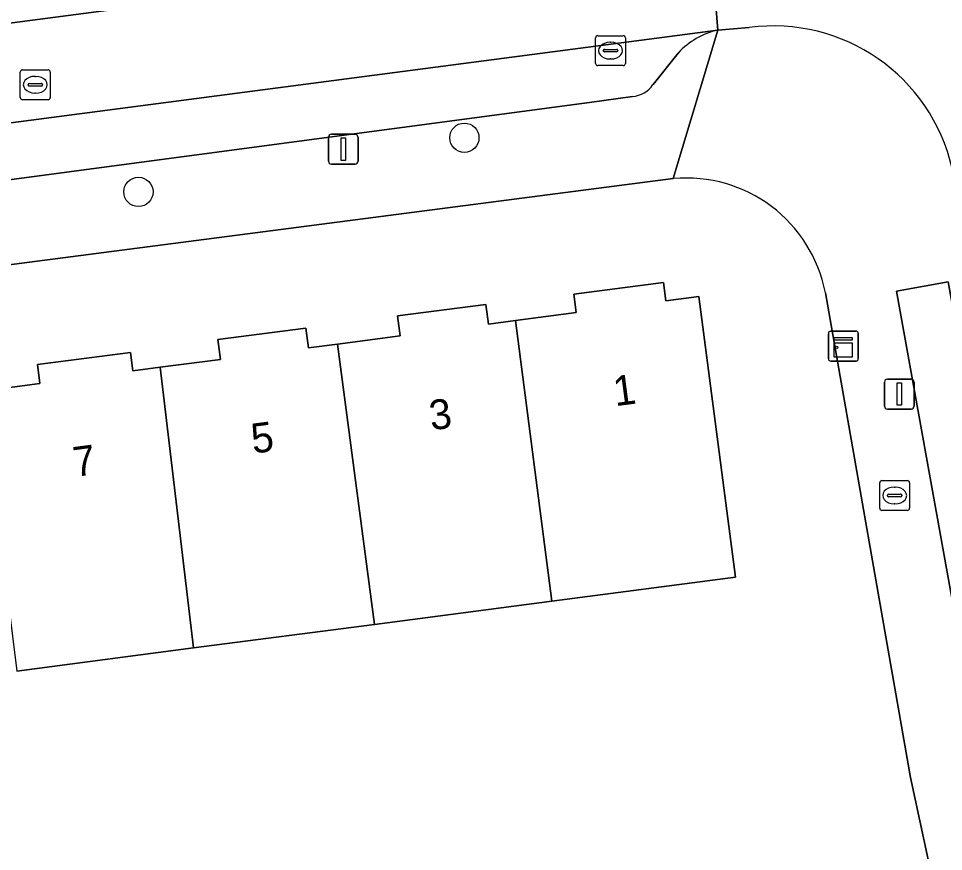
# Model space of a CAD drawing. Extents: x 162073 to 163043, y 381818 to 382561.
# Drawn here: x 162440.71 to 162471.64, y 382437.39 to 382465.27 of the extents above; entities that cross this region are included whole.
import ezdxf

# ---------------------------------------------------------------- set-up
doc = ezdxf.new("R2010")
doc.units = 0
for name, color, linetype in [('IMGEO_Boom', 7, 'Continuous'), ('IMGEO_Brandkraan', 7, 'Continuous'), ('IMGEO_Erf', 7, 'Continuous'), ('IMGEO_Kast', 7, 'Continuous'), ('IMGEO_Kolk', 7, 'Continuous'), ('IMGEO_Lichtmast', 7, 'Continuous'), ('IMGEO_Pand', 7, 'Continuous'), ('IMGEO_Pand_nummerreeks', 7, 'Continuous'), ('IMGEO_Parkeervlak_open', 7, 'Continuous'), ('IMGEO_Rijbaan_lokaal_open', 7, 'Continuous'), ('IMGEO_Rioolput', 7, 'Continuous'), ('IMGEO_Voetpad_open', 7, 'Continuous')]:
    doc.layers.add(name, color=color, linetype=linetype)

msp = doc.modelspace()

# ---------------------------------------------------------------- linework, layer by layer
at = {"layer": 'IMGEO_Boom'}
for centre in [(162455.618, 382461.278), (162444.718, 382459.465)]:
    msp.add_circle(centre, 0.489, dxfattribs=at)
at = {"layer": 'IMGEO_Brandkraan'}
for p, q in [((162469.51, 382448.881), (162469.51, 382449.733)), ((162469.585, 382449.807), (162470.437, 382449.807)), ((162469.998, 382449.587), (162470.023, 382449.587)), ((162470.511, 382449.733), (162470.511, 382448.881)), ((162469.769, 382449.301), (162469.769, 382449.313)), ((162470.207, 382449.264), (162469.809, 382449.264)), ((162469.812, 382449.35), (162470.21, 382449.35)), ((162470.253, 382449.313), (162470.253, 382449.301)), ((162470.021, 382449.027), (162469.996, 382449.027)), ((162470.437, 382448.807), (162469.585, 382448.807))]:
    msp.add_line(p, q, dxfattribs=at)
for points in [[(162469.51, 382448.881), (162469.51, 382449.733)], [(162469.585, 382449.807), (162470.437, 382449.807)], [(162470.511, 382449.733), (162470.511, 382448.881)], [(162470.437, 382448.807), (162469.585, 382448.807)]]:
    msp.add_lwpolyline(points, dxfattribs=at)
for centre, radius, start, end in [((162469.587, 382449.731), 0.0765, 91.552, 178.448), ((162469.587, 382449.731), 0.0765, 91.552, 178.448), ((162470.435, 382449.731), 0.0765, 1.552, 88.448), ((162470.435, 382449.731), 0.0765, 1.552, 88.448), ((162469.809, 382449.31), 0.0403, 85.8775, 175.7526), ((162469.806, 382449.3), 0.0366, 178.938, 274.7102), ((162470.21, 382449.307), 0.043, 264.8664, 352.4533), ((162470.214, 382449.312), 0.0386, 1.7309, 96.639), ((162469.587, 382448.883), 0.0765, 181.552, 268.448), ((162469.587, 382448.883), 0.0765, 181.552, 268.448), ((162470.435, 382448.883), 0.0765, 271.552, 358.448), ((162470.435, 382448.883), 0.0765, 271.552, 358.448)]:
    msp.add_arc(centre, radius, start, end, dxfattribs=at)
for centre, major_axis, ratio, start_param, end_param in [((162469.997, 382449.307), (-0.387, 0.002), 0.722429, 4.712389, 7.853982), ((162470.022, 382449.307), (-0.39, 0.002), 0.717154, 1.570796, 4.712389)]:
    msp.add_ellipse(centre, major_axis=major_axis, ratio=ratio, start_param=start_param, end_param=end_param, dxfattribs=at)
at = {"layer": 'IMGEO_Erf'}
for points in [[(162462.605, 382459.91), (162419.532, 382454.313)], [(162439.485, 382452.801), (162441.425, 382453.054), (162441.342, 382453.686), (162444.448, 382454.092), (162444.528, 382453.477), (162445.442, 382453.596), (162447.457, 382453.859), (162447.37, 382454.522), (162450.313, 382454.907), (162450.4, 382454.245), (162451.381, 382454.373), (162453.466, 382454.645), (162453.378, 382455.317), (162456.341, 382455.704), (162456.427, 382455.043), (162457.334, 382455.161), (162459.363, 382455.426), (162459.283, 382456.039), (162462.281, 382456.43), (162462.36, 382455.825), (162463.456, 382455.968), (162464.683, 382446.57), (162458.546, 382445.769), (162452.608, 382444.993), (162446.564, 382444.204), (162440.645, 382443.431)], [(162470.542, 382439.866), (162467.692, 382456.09)], [(162471.443, 382435.682), (162470.542, 382439.866)]]:
    msp.add_lwpolyline(points, dxfattribs=at)
msp.add_arc((162463.044, 382455.197), 4.733, 10.8729, 95.3188, dxfattribs=at)
at = {"layer": 'IMGEO_Kast'}
for p, q in [((162467.868, 382454.805), (162468.709, 382454.805)), ((162468.709, 382454.805), (162467.868, 382454.805)), ((162467.793, 382453.88), (162467.793, 382454.721)), ((162467.793, 382454.721), (162467.793, 382453.88)), ((162468.793, 382454.73), (162468.793, 382453.889)), ((162468.793, 382453.889), (162468.793, 382454.73)), ((162468.718, 382453.805), (162467.877, 382453.805)), ((162467.877, 382453.805), (162468.718, 382453.805))]:
    msp.add_line(p, q, dxfattribs=at)
for points in [[(162467.988, 382454.595), (162468.588, 382454.595), (162468.588, 382454.51), (162467.988, 382454.51), (162467.988, 382454.595)], [(162467.988, 382454.42), (162468.588, 382454.42), (162468.588, 382453.931), (162467.988, 382453.931), (162467.988, 382454.42)]]:
    msp.add_lwpolyline(points, dxfattribs=at)
msp.add_circle((162468.072, 382454.269), 0.0377, dxfattribs=at)
for centre, start, end in [((162467.871, 382454.727), 92.4484, 184.2845), ((162467.871, 382454.727), 92.4484, 184.2845), ((162468.715, 382454.727), 2.4484, 94.2845), ((162468.715, 382454.727), 2.4484, 94.2845), ((162467.871, 382453.883), 182.4484, 274.2845), ((162467.871, 382453.883), 182.4484, 274.2845), ((162468.715, 382453.883), 272.4484, 4.2845), ((162468.715, 382453.883), 272.4484, 4.2845)]:
    msp.add_arc(centre, 0.0779, start, end, dxfattribs=at)
at = {"layer": 'IMGEO_Kolk'}
for p, q in [((162460.007, 382463.768), (162460.007, 382464.62)), ((162460.082, 382464.694), (162460.934, 382464.694)), ((162460.495, 382464.474), (162460.52, 382464.474)), ((162461.008, 382464.62), (162461.008, 382463.768)), ((162460.266, 382464.188), (162460.266, 382464.2)), ((162460.704, 382464.151), (162460.306, 382464.151)), ((162460.309, 382464.237), (162460.707, 382464.237)), ((162460.75, 382464.2), (162460.75, 382464.188)), ((162460.518, 382463.914), (162460.493, 382463.914)), ((162460.934, 382463.694), (162460.082, 382463.694))]:
    msp.add_line(p, q, dxfattribs=at)
for points in [[(162460.007, 382463.768), (162460.007, 382464.62)], [(162460.082, 382464.694), (162460.934, 382464.694)], [(162461.008, 382464.62), (162461.008, 382463.768)], [(162460.934, 382463.694), (162460.082, 382463.694)]]:
    msp.add_lwpolyline(points, dxfattribs=at)
for centre, radius, start, end in [((162460.084, 382464.618), 0.0765, 91.552, 178.448), ((162460.084, 382464.618), 0.0765, 91.552, 178.448), ((162460.932, 382464.618), 0.0765, 1.552, 88.448), ((162460.932, 382464.618), 0.0765, 1.552, 88.448), ((162460.306, 382464.197), 0.0403, 85.8775, 175.7526), ((162460.303, 382464.187), 0.0366, 178.938, 274.7102), ((162460.707, 382464.194), 0.043, 264.8664, 352.4533), ((162460.711, 382464.199), 0.0386, 1.7309, 96.639), ((162460.084, 382463.77), 0.0765, 181.552, 268.448), ((162460.084, 382463.77), 0.0765, 181.552, 268.448), ((162460.932, 382463.77), 0.0765, 271.552, 358.448), ((162460.932, 382463.77), 0.0765, 271.552, 358.448)]:
    msp.add_arc(centre, radius, start, end, dxfattribs=at)
for centre, major_axis, ratio, start_param, end_param in [((162460.494, 382464.194), (-0.387, 0.002), 0.722429, 4.712389, 7.853982), ((162460.519, 382464.194), (-0.39, 0.002), 0.717154, 1.570796, 4.712389)]:
    msp.add_ellipse(centre, major_axis=major_axis, ratio=ratio, start_param=start_param, end_param=end_param, dxfattribs=at)
at = {"layer": 'IMGEO_Lichtmast'}
for p, q in [((162451.073, 382460.496), (162451.073, 382461.296)), ((162451.073, 382461.296), (162451.073, 382460.496)), ((162451.173, 382461.396), (162451.963, 382461.396)), ((162451.963, 382461.396), (162451.173, 382461.396)), ((162452.063, 382461.296), (162452.063, 382460.496)), ((162452.063, 382460.496), (162452.063, 382461.296)), ((162451.963, 382460.396), (162451.173, 382460.396)), ((162451.173, 382460.396), (162451.963, 382460.396)), ((162469.669, 382452.3), (162469.669, 382453.1)), ((162469.669, 382453.1), (162469.669, 382452.3)), ((162469.769, 382453.2), (162470.559, 382453.2)), ((162470.559, 382453.2), (162469.769, 382453.2)), ((162470.659, 382453.1), (162470.659, 382452.3)), ((162470.659, 382452.3), (162470.659, 382453.1)), ((162470.559, 382452.2), (162469.769, 382452.2)), ((162469.769, 382452.2), (162470.559, 382452.2))]:
    msp.add_line(p, q, dxfattribs=at)
for points in [[(162451.493, 382461.271), (162451.643, 382461.271), (162451.643, 382460.521), (162451.493, 382460.521), (162451.493, 382461.271)], [(162470.089, 382453.075), (162470.239, 382453.075), (162470.239, 382452.325), (162470.089, 382452.325), (162470.089, 382453.075)]]:
    msp.add_lwpolyline(points, dxfattribs=at)
for centre, start, end in [((162451.173, 382461.296), 90, 180), ((162451.173, 382461.296), 90, 180), ((162451.963, 382461.296), 0, 90), ((162451.963, 382461.296), 360, 90), ((162451.173, 382460.496), 180, 270), ((162451.173, 382460.496), 180, 270), ((162451.963, 382460.496), 270, 0), ((162451.963, 382460.496), 270, 0), ((162469.769, 382453.1), 90, 180), ((162469.769, 382453.1), 90, 180), ((162470.559, 382453.1), 0, 90), ((162470.559, 382453.1), 360, 90), ((162469.769, 382452.3), 180, 270), ((162469.769, 382452.3), 180, 270), ((162470.559, 382452.3), 270, 0), ((162470.559, 382452.3), 270, 0)]:
    msp.add_arc(centre, 0.1, start, end, dxfattribs=at)
at = {"layer": 'IMGEO_Pand'}
for points in [[(162457.334, 382455.161), (162458.546, 382445.769), (162464.683, 382446.57), (162463.456, 382455.968), (162462.36, 382455.825), (162462.281, 382456.43), (162459.283, 382456.039), (162459.363, 382455.426)], [(162457.334, 382455.161), (162456.427, 382455.043), (162456.341, 382455.704), (162453.378, 382455.317), (162453.466, 382454.645), (162451.381, 382454.373), (162452.608, 382444.993), (162458.546, 382445.769)], [(162451.381, 382454.373), (162450.4, 382454.245), (162450.313, 382454.907), (162447.37, 382454.522), (162447.457, 382453.859), (162445.442, 382453.596), (162446.564, 382444.204), (162452.608, 382444.993)], [(162439.485, 382452.801), (162440.645, 382443.431), (162446.564, 382444.204), (162445.442, 382453.596), (162444.528, 382453.477), (162444.448, 382454.092), (162441.342, 382453.686), (162441.425, 382453.054)]]:
    msp.add_lwpolyline(points, close=True, dxfattribs=at)
at = {"layer": 'IMGEO_Parkeervlak_open'}
for points in [[(162354.468, 382453.854), (162463.823, 382468.189)], [(162464.101, 382464.878), (162416.788, 382458.681)], [(162461.928, 382463.058), (162462.77, 382464.113)], [(162459.803, 382462.461), (162461.243, 382462.662)], [(162419.794, 382457.129), (162459.803, 382462.461)]]:
    msp.add_lwpolyline(points, dxfattribs=at)
msp.add_lwpolyline([(162472.626, 382441.979), (162474.352, 382442.289), (162471.802, 382456.455), (162470.076, 382456.144)], close=True, dxfattribs=at)
for centre, radius, start, end in [((162464.635, 382462.408), 2.527, 102.2076, 137.5692), ((162461.185, 382463.552), 0.892, 273.7032, 326.3614)]:
    msp.add_arc(centre, radius, start, end, dxfattribs=at)
at = {"layer": 'IMGEO_Rijbaan_lokaal_open'}
msp.add_lwpolyline([(162464.101, 382464.878), (162463.823, 382468.189), (162354.468, 382453.854), (162351.85, 382453.585), (162352.256, 382450.197), (162352.352, 382450.204), (162352.448, 382450.209), (162401.436, 382456.696), (162401.618, 382456.72), (162416.452, 382458.635), (162416.788, 382458.681)], close=True, dxfattribs=at)
msp.add_lwpolyline([(162464.887, 382468.381), (162463.823, 382468.189), (162464.101, 382464.878), (162465.147, 382464.964)], dxfattribs=at)
msp.add_arc((162465.96, 382458.894), 6.124, 12.8212, 97.6244, dxfattribs=at)
at = {"layer": 'IMGEO_Rioolput'}
for p, q in [((162440.767, 382462.626), (162440.767, 382463.478)), ((162440.842, 382463.552), (162441.694, 382463.552)), ((162441.768, 382463.478), (162441.768, 382462.626)), ((162441.255, 382463.332), (162441.28, 382463.332)), ((162441.026, 382463.046), (162441.026, 382463.058)), ((162441.464, 382463.009), (162441.066, 382463.009)), ((162441.069, 382463.095), (162441.467, 382463.095)), ((162441.51, 382463.058), (162441.51, 382463.046)), ((162441.694, 382462.552), (162440.842, 382462.552)), ((162441.278, 382462.772), (162441.253, 382462.772))]:
    msp.add_line(p, q, dxfattribs=at)
for points in [[(162440.767, 382462.626), (162440.767, 382463.478)], [(162440.842, 382463.552), (162441.694, 382463.552)], [(162441.768, 382463.478), (162441.768, 382462.626)], [(162441.694, 382462.552), (162440.842, 382462.552)]]:
    msp.add_lwpolyline(points, dxfattribs=at)
for centre, radius, start, end in [((162440.844, 382463.476), 0.0765, 91.552, 178.448), ((162440.844, 382463.476), 0.0765, 91.552, 178.448), ((162441.692, 382463.476), 0.0765, 1.552, 88.448), ((162441.692, 382463.476), 0.0765, 1.552, 88.448), ((162441.066, 382463.055), 0.0403, 85.8775, 175.7526), ((162441.063, 382463.045), 0.0366, 178.938, 274.7102), ((162441.467, 382463.052), 0.043, 264.8664, 352.4533), ((162441.471, 382463.057), 0.0386, 1.7309, 96.639), ((162440.844, 382462.628), 0.0765, 181.552, 268.448), ((162440.844, 382462.628), 0.0765, 181.552, 268.448), ((162441.692, 382462.628), 0.0765, 271.552, 358.448), ((162441.692, 382462.628), 0.0765, 271.552, 358.448)]:
    msp.add_arc(centre, radius, start, end, dxfattribs=at)
for centre, major_axis, ratio, start_param, end_param in [((162441.254, 382463.052), (-0.387, 0.002), 0.722429, 4.712389, 7.853982), ((162441.279, 382463.052), (-0.39, 0.002), 0.717154, 1.570796, 4.712389)]:
    msp.add_ellipse(centre, major_axis=major_axis, ratio=ratio, start_param=start_param, end_param=end_param, dxfattribs=at)
at = {"layer": 'IMGEO_Voetpad_open'}
for points in [[(162465.147, 382464.964), (162464.101, 382464.878), (162462.605, 382459.91)], [(162462.605, 382459.91), (162464.101, 382464.878)], [(162462.77, 382464.113), (162461.928, 382463.058)], [(162461.243, 382462.662), (162459.803, 382462.461), (162419.794, 382457.129)], [(162411.117, 382453.202), (162419.532, 382454.313), (162462.605, 382459.91)], [(162467.692, 382456.09), (162470.542, 382439.866), (162471.443, 382435.682), (162471.766, 382434.181), (162474.011, 382423.75), (162475.605, 382417.116), (162480.443, 382399.863), (162480.629, 382399.2), (162480.865, 382398.456), (162483.369, 382390.549)]]:
    msp.add_lwpolyline(points, dxfattribs=at)
msp.add_lwpolyline([(162474.352, 382442.289), (162472.626, 382441.979), (162470.076, 382456.144), (162471.802, 382456.455)], close=True, dxfattribs=at)
for centre, radius, start, end in [((162465.96, 382458.894), 6.124, 12.8212, 97.6244), ((162464.635, 382462.408), 2.527, 102.2076, 137.5692), ((162461.185, 382463.552), 0.892, 273.7032, 326.3614), ((162463.044, 382455.197), 4.733, 10.8729, 95.3188)]:
    msp.add_arc(centre, radius, start, end, dxfattribs=at)

# ---------------------------------------------------------------- texts
at = {"layer": 'IMGEO_Pand_nummerreeks'}
for s, rotation, p in [('1', 7.5065, (162460.664, 382452.292)), ('3', 7.4443, (162454.509, 382451.484)), ('5', 7.4443, (162448.553, 382450.705)), ('7', 7.4443, (162442.596, 382449.927))]:
    msp.add_text(s, height=1, rotation=rotation, dxfattribs=at).set_placement(p)

doc.saveas('drawing.dxf')
